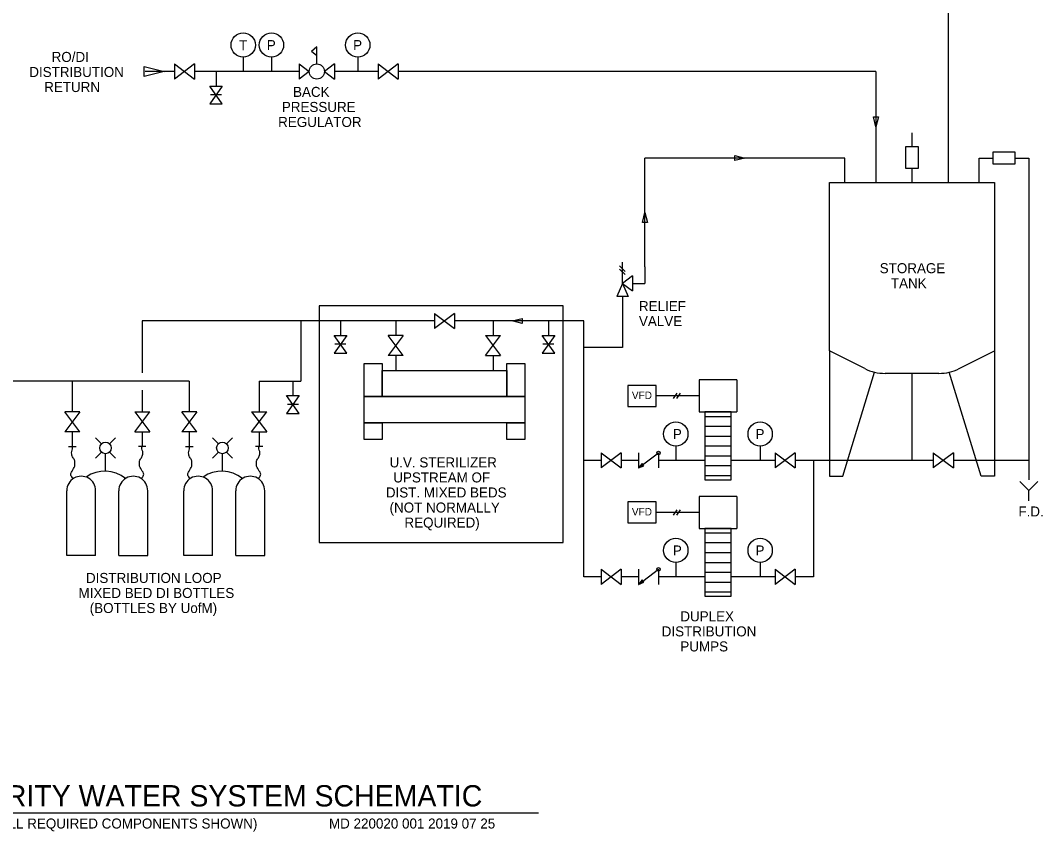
# Model space of a CAD drawing. Extents: x 9934 to 10051, y 10032 to 10115.
# Drawn here: x 9982.7 to 10050.7, y 10032.2 to 10086.2 of the extents above; entities that cross this region are included whole.
import ezdxf

# ---------------------------------------------------------------- set-up
doc = ezdxf.new("R2010")
doc.units = 0
for name, color, linetype in [('G-ANNO-CELL', 7, 'Continuous'), ('G-ANNO-TEXT', 7, 'Continuous'), ('M-CELL', 7, 'Continuous'), ('M-EQPM', 7, 'Continuous'), ('M-STEM-CONP', 7, 'Continuous'), ('P-LGAS-PIPE', 7, 'Continuous'), ('P-PURE-PIPE', 7, 'Continuous')]:
    doc.layers.add(name, color=color, linetype=linetype)

msp = doc.modelspace()

# ---------------------------------------------------------------- linework, layer by layer
at = {"layer": 'G-ANNO-CELL'}
msp.add_line((9971.642, 10033.467), (10017.188, 10033.467), dxfattribs=at)
at = {"layer": 'G-ANNO-TEXT'}
for p, q in [((9997.558, 10083.713), (9997.558, 10082.759)), ((9999.437, 10083.713), (9999.437, 10082.759)), ((10005.177, 10083.713), (10005.177, 10082.759)), ((10042.02, 10078.688), (10042.02, 10077.763)), ((10037.555, 10077), (10024.266, 10077)), ((10024.266, 10069.783), (10024.266, 10077)), ((10037.555, 10075.384), (10037.555, 10077)), ((10046.486, 10075.384), (10046.486, 10077)), ((10046.486, 10077), (10047.411, 10077)), ((10048.865, 10077), (10049.79, 10077)), ((10049.79, 10077), (10049.79, 10055.61)), ((10042.02, 10076.309), (10042.02, 10075.384)), ((10036.531, 10075.384), (10047.509, 10075.384)), ((10036.531, 10064.184), (10036.531, 10075.384)), ((10047.509, 10075.384), (10047.509, 10064.184)), ((10022.768, 10068.677), (10022.768, 10070.095)), ((10022.952, 10069.471), (10022.584, 10069.839)), ((10022.952, 10069.257), (10022.584, 10069.625)), ((10022.768, 10068.677), (10022.393, 10067.812)), ((10023.435, 10069.177), (10022.768, 10068.677)), ((10022.768, 10068.677), (10023.435, 10068.177)), ((10022.768, 10068.677), (10023.143, 10067.812)), ((10023.435, 10069.177), (10023.435, 10068.177)), ((10023.435, 10068.677), (10024.266, 10068.677)), ((10023.143, 10067.812), (10022.393, 10067.812)), ((10022.768, 10067.812), (10022.768, 10064.411)), ((10022.768, 10064.411), (10020.198, 10064.411)), ((10038.886, 10063.007), (10036.531, 10064.184)), ((10036.531, 10064.184), (10036.531, 10055.851)), ((10045.155, 10063.007), (10047.509, 10064.184)), ((10047.509, 10064.184), (10047.509, 10055.851)), ((10037.422, 10055.851), (10039.538, 10062.771)), ((10043.813, 10062.691), (10040.227, 10062.691)), ((10046.618, 10055.851), (10044.503, 10062.771)), ((10027.873, 10062.252), (10027.873, 10060.126)), ((10030.374, 10062.252), (10027.873, 10062.252)), ((10030.374, 10062.252), (10030.374, 10060.126)), ((10027.873, 10061.189), (10025.013, 10061.189)), ((10026.384, 10061.366), (10026.153, 10061.014)), ((10026.598, 10061.366), (10026.367, 10061.014)), ((10027.873, 10060.126), (10030.374, 10060.126)), ((10028.238, 10059.831), (10030.009, 10059.831)), ((10028.238, 10059.177), (10030.009, 10059.177)), ((10028.238, 10058.522), (10030.009, 10058.522)), ((10026.319, 10057.857), (10026.319, 10056.903)), ((10028.238, 10057.868), (10030.009, 10057.868)), ((10031.928, 10057.857), (10031.928, 10056.903)), ((10028.238, 10057.213), (10030.009, 10057.213)), ((10043.437, 10057.403), (10043.437, 10056.403)), ((10044.771, 10057.403), (10043.437, 10056.403)), ((10043.437, 10057.403), (10044.771, 10056.403)), ((10044.771, 10057.403), (10044.771, 10056.403)), ((10028.238, 10056.559), (10030.009, 10056.559)), ((10043.437, 10056.903), (10042.02, 10056.903)), ((10049.79, 10056.903), (10044.771, 10056.903)), ((10028.238, 10055.904), (10030.009, 10055.904)), ((10036.531, 10055.851), (10037.422, 10055.851)), ((10047.509, 10055.851), (10046.618, 10055.851)), ((10049.79, 10054.908), (10049.186, 10055.511)), ((10049.79, 10054.908), (10050.394, 10055.511)), ((9985.826, 10050.592), (9985.826, 10054.892)), ((9987.748, 10050.592), (9987.748, 10054.892)), ((9989.289, 10050.592), (9989.289, 10054.892)), ((9991.211, 10050.592), (9991.211, 10054.892)), ((9993.602, 10050.592), (9993.602, 10054.892)), ((9995.524, 10050.592), (9995.524, 10054.892)), ((9997.065, 10050.592), (9997.065, 10054.892)), ((9998.987, 10050.592), (9998.987, 10054.892)), ((10027.873, 10054.512), (10027.873, 10052.386)), ((10030.374, 10054.512), (10027.873, 10054.512)), ((10030.374, 10054.512), (10030.374, 10052.386)), ((10049.79, 10054.209), (10049.79, 10054.908)), ((10027.873, 10053.449), (10025.013, 10053.449)), ((10026.384, 10053.626), (10026.153, 10053.274)), ((10026.598, 10053.626), (10026.367, 10053.274)), ((10027.873, 10052.386), (10030.374, 10052.386)), ((10028.238, 10052.091), (10030.009, 10052.091)), ((10028.238, 10051.437), (10030.009, 10051.437)), ((9987.748, 10050.592), (9985.826, 10050.592)), ((9989.289, 10050.592), (9991.211, 10050.592)), ((9995.524, 10050.592), (9993.602, 10050.592)), ((9997.065, 10050.592), (9998.987, 10050.592)), ((10028.238, 10050.782), (10030.009, 10050.782)), ((10026.319, 10050.117), (10026.319, 10049.164)), ((10028.238, 10050.128), (10030.009, 10050.128)), ((10031.928, 10050.117), (10031.928, 10049.164)), ((10028.238, 10049.473), (10030.009, 10049.473)), ((10028.238, 10048.819), (10030.009, 10048.819)), ((10028.238, 10048.164), (10030.009, 10048.164))]:
    msp.add_line(p, q, dxfattribs=at)
for points in [[(10042.431, 10077.763), (10042.431, 10076.309), (10041.609, 10076.309), (10041.609, 10077.763)], [(10047.411, 10077.411), (10048.865, 10077.411), (10048.865, 10076.589), (10047.411, 10076.589)], [(10018.841, 10067.188), (10002.613, 10067.188), (10002.613, 10051.455), (10018.841, 10051.455)], [(10006.807, 10061.147), (10005.606, 10061.147), (10005.606, 10063.348), (10006.807, 10063.348)], [(10016.279, 10061.147), (10015.078, 10061.147), (10015.078, 10063.348), (10016.279, 10063.348)], [(10006.807, 10062.881), (10015.078, 10062.881), (10015.078, 10061.147), (10006.807, 10061.147)], [(10023.123, 10060.497), (10025.013, 10060.497), (10025.013, 10061.882), (10023.123, 10061.882)], [(10005.606, 10061.147), (10016.279, 10061.147), (10016.279, 10059.412), (10005.606, 10059.412)], [(10028.238, 10055.609), (10030.009, 10055.609), (10030.009, 10060.126), (10028.238, 10060.126)], [(10005.606, 10059.412), (10006.799, 10059.412), (10006.799, 10058.297), (10005.606, 10058.297)], [(10015.085, 10059.412), (10016.279, 10059.412), (10016.279, 10058.297), (10015.085, 10058.297)], [(10023.123, 10052.757), (10025.013, 10052.757), (10025.013, 10054.142), (10023.123, 10054.142)], [(10028.238, 10047.869), (10030.009, 10047.869), (10030.009, 10052.386), (10028.238, 10052.386)]]:
    msp.add_lwpolyline(points, close=True, dxfattribs=at)
for centre in [(9997.558, 10084.521), (9999.437, 10084.521), (10005.177, 10084.521), (10026.319, 10058.665), (10031.928, 10058.665), (10026.319, 10050.925), (10031.928, 10050.925)]:
    msp.add_circle(centre, 0.808, dxfattribs=at)
for centre, radius, start, end in [((10040.227, 10065.691), 3, 243.43495, 270), ((10043.813, 10065.691), 3, 270, 296.56505), ((9986.787, 10054.892), 0.961, 0, 180.00009), ((9990.25, 10054.892), 0.961, 359.99991, 180), ((9994.563, 10054.892), 0.961, 0, 180.00009), ((9998.026, 10054.892), 0.961, 359.99991, 180)]:
    msp.add_arc(centre, radius, start, end, dxfattribs=at)
at = {"layer": 'M-CELL'}
msp.add_line((10024.266, 10069.783), (10024.266, 10068.676), dxfattribs=at)
at = {"layer": 'M-EQPM'}
for points in [[(10030.244, 10077.166), (10030.91, 10077), (10030.244, 10076.833)], [(10024.099, 10072.724), (10024.266, 10073.391), (10024.432, 10072.724)]]:
    msp.add_lwpolyline(points, close=True, dxfattribs=at)
at = {"layer": 'M-STEM-CONP'}
msp.add_line((10044.42, 10106.03), (10044.42, 10075.384), dxfattribs=at)
at = {"layer": 'P-LGAS-PIPE'}
for p, q in [((10002.453, 10084.391), (10002.103, 10084.1)), ((10002.453, 10083.259), (10002.453, 10084.391)), ((10002.453, 10083.81), (10002.103, 10084.1)), ((9992.982, 10083.259), (9992.982, 10082.259)), ((9992.982, 10083.259), (9994.316, 10082.259)), ((9994.316, 10083.259), (9992.982, 10082.259)), ((9994.316, 10083.259), (9994.316, 10082.259)), ((10001.286, 10083.259), (10001.286, 10082.259)), ((10001.286, 10083.259), (10001.953, 10082.759)), ((10003.619, 10083.259), (10002.953, 10082.759)), ((10003.619, 10083.259), (10003.619, 10082.259)), ((10006.521, 10083.259), (10006.521, 10082.259)), ((10006.521, 10083.259), (10007.854, 10082.259)), ((10007.854, 10083.259), (10006.521, 10082.259)), ((10007.854, 10083.259), (10007.854, 10082.259)), ((9992.982, 10082.759), (9991.036, 10082.759)), ((10001.286, 10082.759), (9994.316, 10082.759)), ((9995.753, 10082.759), (9995.753, 10081.795)), ((10001.953, 10082.759), (10001.286, 10082.259)), ((10002.953, 10082.759), (10003.619, 10082.259)), ((10006.521, 10082.759), (10003.619, 10082.759)), ((10039.62, 10082.759), (10007.854, 10082.759)), ((10039.62, 10082.759), (10039.62, 10075.384)), ((9995.337, 10081.795), (9996.17, 10081.795)), ((9996.17, 10081.795), (9995.337, 10080.605)), ((9996.17, 10080.605), (9995.337, 10081.795)), ((9996.118, 10081.2), (9995.388, 10081.2)), ((9995.337, 10080.605), (9996.17, 10080.605))]:
    msp.add_line(p, q, dxfattribs=at)
for points in [[(9990.978, 10083.093), (9992.311, 10082.759), (9990.978, 10082.426)], [(10039.787, 10079.738), (10039.62, 10079.072), (10039.453, 10079.738)]]:
    msp.add_lwpolyline(points, close=True, dxfattribs=at)
msp.add_circle((10002.453, 10082.759), 0.5, dxfattribs=at)
at = {"layer": 'P-PURE-PIPE'}
for p, q in [((10010.276, 10066.681), (10010.276, 10065.681)), ((10010.276, 10066.681), (10011.609, 10065.681)), ((10011.609, 10066.681), (10010.276, 10065.681)), ((10011.609, 10066.681), (10011.609, 10065.681)), ((10010.276, 10066.181), (9990.843, 10066.181)), ((9990.843, 10066.181), (9990.843, 10062.738)), ((10001.381, 10066.181), (10001.381, 10062.183)), ((10004.028, 10066.181), (10004.028, 10065.217)), ((10007.697, 10066.181), (10007.697, 10065.217)), ((10020.198, 10066.181), (10011.609, 10066.181)), ((10014.174, 10066.181), (10014.174, 10065.217)), ((10017.857, 10066.181), (10017.857, 10065.217)), ((10020.198, 10049.164), (10020.198, 10066.181)), ((10003.611, 10065.217), (10004.444, 10065.217)), ((10004.444, 10065.217), (10003.611, 10064.026)), ((10004.444, 10064.026), (10003.611, 10065.217)), ((10004.378, 10064.622), (10003.648, 10064.622)), ((10008.197, 10065.217), (10007.197, 10065.217)), ((10008.197, 10065.217), (10007.197, 10063.884)), ((10008.197, 10063.884), (10007.197, 10065.217)), ((10013.674, 10065.217), (10014.674, 10065.217)), ((10013.674, 10065.217), (10014.674, 10063.884)), ((10013.674, 10063.884), (10014.674, 10065.217)), ((10017.44, 10065.217), (10018.274, 10065.217)), ((10018.274, 10065.217), (10017.44, 10064.026)), ((10018.274, 10064.026), (10017.44, 10065.217)), ((10018.207, 10064.622), (10017.477, 10064.622)), ((10003.611, 10064.026), (10004.444, 10064.026)), ((10008.197, 10063.884), (10007.197, 10063.884)), ((10007.697, 10063.884), (10007.697, 10062.923)), ((10013.674, 10063.884), (10014.674, 10063.884)), ((10014.174, 10063.884), (10014.174, 10062.923)), ((10017.44, 10064.026), (10018.274, 10064.026)), ((10042.02, 10062.691), (10042.02, 10056.903)), ((9993.971, 10062.183), (9976.219, 10062.183)), ((9986.195, 10062.183), (9986.195, 10060.132)), ((9993.971, 10062.183), (9993.971, 10060.132)), ((9998.619, 10062.183), (9998.619, 10060.132)), ((9998.619, 10062.183), (10001.381, 10062.183)), ((10000.861, 10062.183), (10000.861, 10061.219)), ((9990.843, 10061.568), (9990.843, 10060.132)), ((10000.444, 10061.219), (10001.277, 10061.219)), ((10001.277, 10061.219), (10000.444, 10060.028)), ((10001.277, 10060.028), (10000.444, 10061.219)), ((10001.226, 10060.623), (10000.495, 10060.623)), ((9986.695, 10060.132), (9985.695, 10060.132)), ((9986.695, 10060.132), (9985.695, 10058.798)), ((9986.695, 10058.798), (9985.695, 10060.132)), ((9990.343, 10060.132), (9991.343, 10060.132)), ((9990.343, 10060.132), (9991.343, 10058.798)), ((9990.343, 10058.798), (9991.343, 10060.132)), ((9994.471, 10060.132), (9993.471, 10060.132)), ((9994.471, 10060.132), (9993.471, 10058.798)), ((9994.471, 10058.798), (9993.471, 10060.132)), ((9998.119, 10060.132), (9999.119, 10060.132)), ((9998.119, 10060.132), (9999.119, 10058.798)), ((9998.119, 10058.798), (9999.119, 10060.132)), ((10000.444, 10060.028), (10001.277, 10060.028)), ((9986.695, 10058.798), (9985.695, 10058.798)), ((9986.195, 10058.798), (9986.195, 10057.838)), ((9990.343, 10058.798), (9991.343, 10058.798)), ((9990.843, 10058.798), (9990.843, 10057.838)), ((9994.471, 10058.798), (9993.471, 10058.798)), ((9993.971, 10058.798), (9993.971, 10057.838)), ((9998.119, 10058.798), (9999.119, 10058.798)), ((9998.619, 10058.798), (9998.619, 10057.838)), ((9985.945, 10057.838), (9986.445, 10057.838)), ((9988.129, 10058.002), (9987.731, 10058.4)), ((9988.67, 10058.002), (9989.068, 10058.4)), ((9991.093, 10057.838), (9990.593, 10057.838)), ((9993.721, 10057.838), (9994.221, 10057.838)), ((9995.905, 10058.002), (9995.507, 10058.4)), ((9996.446, 10058.002), (9996.844, 10058.4)), ((9998.869, 10057.838), (9998.369, 10057.838)), ((9987.731, 10057.063), (9988.129, 10057.461)), ((9988.399, 10056.194), (9988.399, 10057.349)), ((9989.068, 10057.063), (9988.67, 10057.461)), ((9995.507, 10057.063), (9995.905, 10057.461)), ((9996.175, 10056.194), (9996.175, 10057.349)), ((9996.844, 10057.063), (9996.446, 10057.461)), ((10021.349, 10057.403), (10021.349, 10056.403)), ((10021.349, 10057.403), (10022.682, 10056.403)), ((10022.682, 10057.403), (10021.349, 10056.403)), ((10022.682, 10057.403), (10022.682, 10056.403)), ((10023.833, 10057.403), (10023.833, 10056.403)), ((10023.833, 10056.403), (10025.166, 10057.403)), ((10025.166, 10057.403), (10025.166, 10056.403)), ((10032.922, 10057.403), (10032.922, 10056.403)), ((10032.922, 10057.403), (10034.256, 10056.403)), ((10034.256, 10057.403), (10032.922, 10056.403)), ((10034.256, 10057.403), (10034.256, 10056.403)), ((10021.349, 10056.903), (10020.198, 10056.903)), ((10023.833, 10056.903), (10022.682, 10056.903)), ((10028.238, 10056.903), (10025.166, 10056.903)), ((10032.922, 10056.903), (10030.009, 10056.903)), ((10042.02, 10056.903), (10034.256, 10056.903)), ((10035.471, 10056.903), (10035.471, 10049.164)), ((10021.349, 10049.664), (10021.349, 10048.664)), ((10021.349, 10049.664), (10022.682, 10048.664)), ((10022.682, 10049.664), (10021.349, 10048.664)), ((10022.682, 10049.664), (10022.682, 10048.664)), ((10023.833, 10049.664), (10023.833, 10048.664)), ((10023.833, 10048.664), (10025.166, 10049.664)), ((10025.166, 10049.664), (10025.166, 10048.664)), ((10032.922, 10049.664), (10032.922, 10048.664)), ((10032.922, 10049.664), (10034.256, 10048.664)), ((10034.256, 10049.664), (10032.922, 10048.664)), ((10034.256, 10049.664), (10034.256, 10048.664)), ((10021.349, 10049.164), (10020.198, 10049.164)), ((10023.833, 10049.164), (10022.682, 10049.164)), ((10028.238, 10049.164), (10025.166, 10049.164)), ((10032.922, 10049.164), (10030.009, 10049.164)), ((10035.471, 10049.164), (10034.256, 10049.164))]:
    msp.add_line(p, q, dxfattribs=at)
for points in [[(10016.101, 10066.014), (10015.434, 10066.181), (10016.101, 10066.348)], [(10024.077, 10056.703), (10023.833, 10056.403), (10024.189, 10056.553)], [(10024.077, 10048.964), (10023.833, 10048.664), (10024.189, 10048.814)]]:
    msp.add_lwpolyline(points, close=True, dxfattribs=at)
for centre, radius in [((9988.399, 10057.732), 0.383), ((9996.175, 10057.732), 0.383), ((10025.166, 10057.403), 0.117), ((10025.166, 10049.664), 0.117)]:
    msp.add_circle(centre, radius, dxfattribs=at)
for centre in [(9988.358, 10054.039), (9996.134, 10054.039)]:
    msp.add_arc(centre, 2.155, 50.4155, 125.36607, dxfattribs=at)
for points in [[(9986.264, 10055.701), (9986.157, 10055.808), (9986.098, 10056.045), (9986.187, 10056.193), (9986.276, 10056.371), (9986.365, 10056.519), (9986.365, 10056.697), (9986.365, 10056.875), (9986.246, 10057.082), (9986.157, 10057.319), (9986.157, 10057.497), (9986.216, 10057.675), (9986.195, 10057.838)], [(9990.773, 10055.701), (9990.88, 10055.808), (9990.939, 10056.045), (9990.85, 10056.193), (9990.761, 10056.371), (9990.673, 10056.519), (9990.673, 10056.697), (9990.673, 10056.875), (9990.791, 10057.082), (9990.88, 10057.319), (9990.88, 10057.497), (9990.821, 10057.675), (9990.843, 10057.838)], [(9994.04, 10055.701), (9993.933, 10055.808), (9993.874, 10056.045), (9993.963, 10056.193), (9994.052, 10056.371), (9994.141, 10056.519), (9994.141, 10056.697), (9994.141, 10056.875), (9994.022, 10057.082), (9993.933, 10057.319), (9993.933, 10057.497), (9993.992, 10057.675), (9993.971, 10057.838)], [(9998.549, 10055.701), (9998.656, 10055.808), (9998.715, 10056.045), (9998.626, 10056.193), (9998.537, 10056.371), (9998.449, 10056.519), (9998.449, 10056.697), (9998.449, 10056.875), (9998.567, 10057.082), (9998.656, 10057.319), (9998.656, 10057.497), (9998.597, 10057.675), (9998.619, 10057.838)]]:
    msp.add_spline(points, degree=3, dxfattribs=at)

# ---------------------------------------------------------------- texts
at = {"layer": 'G-ANNO-CELL'}
msp.add_text('HIGH PURITY WATER SYSTEM SCHEMATIC', height=1.41667, dxfattribs=at).set_placement((9973.881, 10033.899))
at = {"layer": 'G-ANNO-TEXT'}
for s, height, rotation, p in [('T', 0.667, 360, (9997.284, 10084.169)), ('P', 0.667, 360, (9999.127, 10084.18)), ('P', 0.667, 360, (10004.867, 10084.18)), ('      RO/DI', 0.66667, 0.00002, (9983.336, 10083.395)), ('DISTRIBUTION', 0.66667, 0.00002, (9983.336, 10082.395)), ('    RETURN', 0.6667, 0.00002, (9983.336, 10081.395)), ('    BACK', 0.6667, 0.00002, (9999.88, 10081.07)), (' PRESSURE', 0.6667, 0.00002, (9999.88, 10080.07)), ('REGULATOR', 0.6667, 0.00002, (9999.88, 10079.07)), ('P', 0.667, 360, (10031.618, 10058.324)), ('P', 0.667, 360, (10031.618, 10050.584)), ('  DISTRIBUTION LOOP', 0.66667, 0.00001, (9986.611, 10048.759)), ('MIXED BED DI BOTTLES', 0.66667, 0.00001, (9986.611, 10047.759)), ('   (BOTTLES BY UofM)', 0.66667, 0.00001, (9986.611, 10046.759))]:
    msp.add_text(s, height=height, rotation=rotation, dxfattribs=at).set_placement(p)
for s, height, p in [('STORAGE', 0.6667, (10039.875, 10069.351)), ('   TANK', 0.6667, (10039.875, 10068.351)), ('RELIEF', 0.6667, (10023.867, 10066.831)), ('VALVE', 0.6667, (10023.867, 10065.831)), ('VFD', 0.5, (10023.398, 10060.983)), ('P', 0.667, (10026.124, 10058.324)), (' U.V. STERILIZER', 0.66667, (10007.041, 10056.44)), ('  UPSTREAM OF', 0.66667, (10007.041, 10055.44)), ('DIST. MIXED BEDS', 0.66667, (10007.041, 10054.44)), (' (NOT NORMALLY', 0.66667, (10007.041, 10053.44)), ('VFD', 0.5, (10023.398, 10053.243)), ('F.D.', 0.6667, (10049.099, 10053.177)), ('     REQUIRED)', 0.66667, (10007.041, 10052.44)), ('P', 0.667, (10026.124, 10050.584)), ('     DUPLEX', 0.66667, (10025.382, 10046.206)), ('DISTRIBUTION', 0.66667, (10025.382, 10045.206)), ('     PUMPS', 0.6667, (10025.382, 10044.206)), ('(NOT ALL REQUIRED COMPONENTS SHOWN)', 0.66667, (9978.936, 10032.432)), ('MD 220020 001 2019 07 25', 0.66667, (10003.26, 10032.432))]:
    msp.add_text(s, height=height, dxfattribs=at).set_placement(p)

doc.saveas('drawing.dxf')
